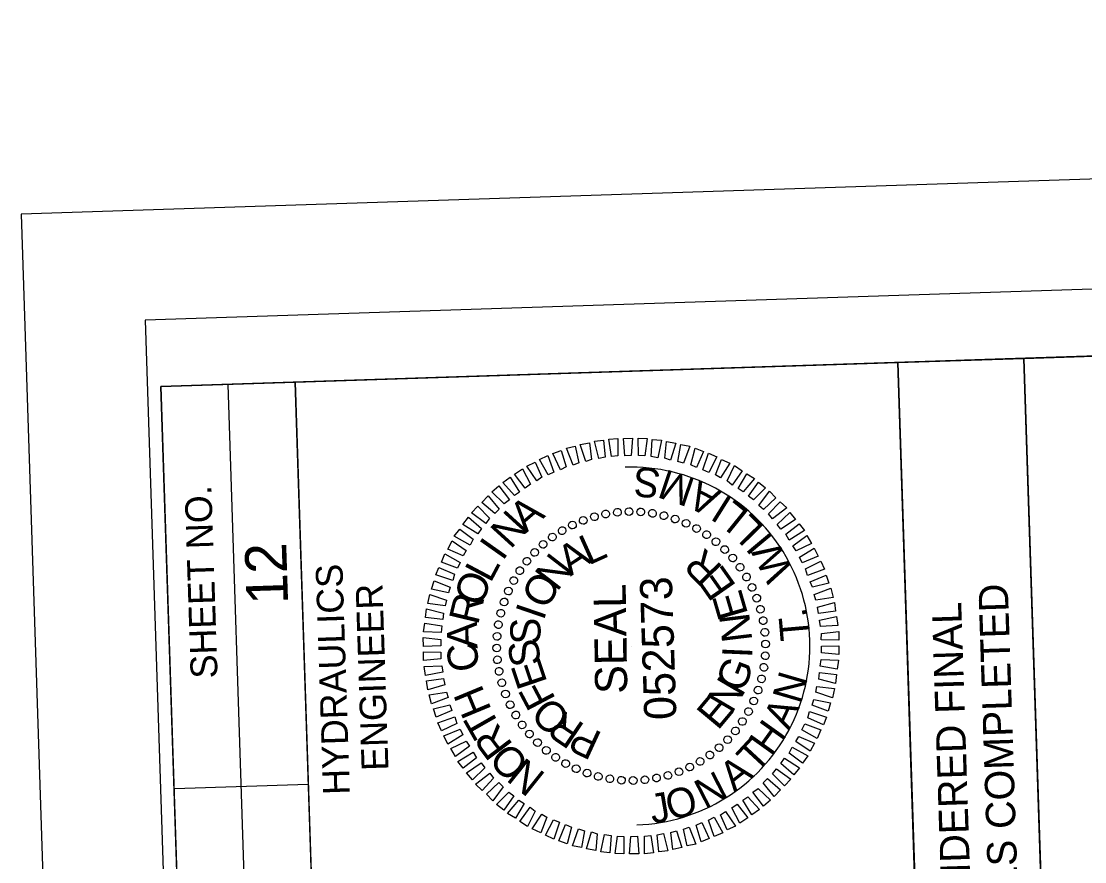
# Model space of a CAD drawing. Extents: x 1627314 to 1628469, y 762309 to 764245.
# Drawn here: x 1627314.2 to 1627512.6, y 763887.6 to 764044.4 of the extents above; entities that cross this region are included whole.
import ezdxf

# ---------------------------------------------------------------- set-up
doc = ezdxf.new("R2010")
doc.units = 0
for name, color, linetype in [('Old_Level_2', 7, 'Continuous'), ('Old_Level_58', 7, 'Continuous'), ('Scratch_Level_0', 7, 'Continuous'), ('Sheet Data Field CELL', 7, 'Continuous'), ('Sheet Plot Border Inside CELL', 7, 'Continuous'), ('Sheet Plot Border Outside CELL', 7, 'Continuous'), ('Sheet Professional Seal CELL', 7, 'Continuous'), ('Sheet Profile CELL', 7, 'Continuous'), ('Sheet Profile Grid Major CELL', 7, 'Continuous'), ('Sheet Profile Grid Minor CELL', 7, 'Continuous'), ('Sheet Sticker Exception Certification CELL', 7, 'Continuous')]:
    doc.layers.add(name, color=color, linetype=linetype)

msp = doc.modelspace()

# ---------------------------------------------------------------- linework, layer by layer
at = {"layer": 'Old_Level_2'}
msp.add_lwpolyline([(1627507.79, 763781.61), (1627501.25, 763981.49), (1627565.16, 763983.58), (1627571.7, 763783.7)], close=True, dxfattribs=at)
at = {"layer": 'Scratch_Level_0'}
msp.add_arc((1627428, 763927.84), 33.36, 271.8735, 91.8735, dxfattribs=at)
at = {"layer": 'Sheet Plot Border Inside CELL'}
msp.add_lwpolyline([(1628446.34, 762357.53), (1628391.86, 764023.14), (1627337.33, 763988.65), (1627391.81, 762323.04)], close=True, dxfattribs=at)
at = {"layer": 'Sheet Plot Border Outside CELL'}
msp.add_lwpolyline([(1628469.21, 762345.27), (1628413.63, 764044.37), (1627314.22, 764008.4), (1627369.79, 762309.31)], close=True, dxfattribs=at)
at = {"layer": 'Sheet Professional Seal CELL'}
for p, q in [((1627421.1, 763951.98), (1627421.1, 763951.98)), ((1627423.29, 763952.45), (1627423.29, 763952.45)), ((1627425.43, 763952.82), (1627425.43, 763952.82)), ((1627427.62, 763952.94), (1627427.62, 763952.94)), ((1627429.83, 763952.86), (1627429.83, 763952.86)), ((1627431.99, 763952.58), (1627431.99, 763952.58)), ((1627434.1, 763952.2), (1627434.1, 763952.2)), ((1627436.22, 763951.57), (1627436.22, 763951.57)), ((1627417.05, 763950.44), (1627417.05, 763950.44)), ((1627419.02, 763951.31), (1627419.02, 763951.31)), ((1627438.25, 763950.74), (1627438.25, 763950.74)), ((1627440.23, 763949.8), (1627440.23, 763949.8)), ((1627413.27, 763948.17), (1627413.27, 763948.17)), ((1627415.13, 763949.38), (1627415.13, 763949.38)), ((1627442.07, 763948.61), (1627442.07, 763948.61)), ((1627411.56, 763946.86), (1627411.56, 763946.86)), ((1627443.87, 763947.32), (1627443.87, 763947.32)), ((1627445.47, 763945.87), (1627445.47, 763945.87)), ((1627408.52, 763943.71), (1627408.52, 763943.71)), ((1627409.96, 763945.31), (1627409.96, 763945.31)), ((1627447.02, 763944.27), (1627447.02, 763944.27)), ((1627407.22, 763941.92), (1627407.22, 763941.92)), ((1627448.33, 763942.56), (1627448.33, 763942.56)), ((1627406.03, 763940.08), (1627406.03, 763940.08)), ((1627449.54, 763940.7), (1627449.54, 763940.7)), ((1627405.1, 763938.1), (1627405.1, 763938.1)), ((1627450.6, 763938.78), (1627450.6, 763938.78)), ((1627404.26, 763936.07), (1627404.26, 763936.07)), ((1627451.46, 763936.81), (1627451.46, 763936.81)), ((1627403.63, 763933.95), (1627403.63, 763933.95)), ((1627452.13, 763934.73), (1627452.13, 763934.73)), ((1627403.25, 763931.83), (1627403.25, 763931.83)), ((1627452.6, 763932.55), (1627452.6, 763932.55)), ((1627402.97, 763929.67), (1627402.97, 763929.67)), ((1627452.98, 763930.41), (1627452.98, 763930.41)), ((1627428, 763927.84), (1627428, 763927.84)), ((1627453.1, 763928.21), (1627453.1, 763928.21)), ((1627402.89, 763927.47), (1627402.89, 763927.47)), ((1627453.02, 763926.01), (1627453.02, 763926.01)), ((1627403.02, 763925.27), (1627403.02, 763925.27)), ((1627452.74, 763923.85), (1627452.74, 763923.85)), ((1627403.39, 763923.13), (1627403.39, 763923.13)), ((1627452.36, 763921.73), (1627452.36, 763921.73)), ((1627403.86, 763920.95), (1627403.86, 763920.95)), ((1627404.53, 763918.87), (1627404.53, 763918.87)), ((1627451.73, 763919.61), (1627451.73, 763919.61)), ((1627405.39, 763916.89), (1627405.39, 763916.89)), ((1627450.89, 763917.58), (1627450.89, 763917.58)), ((1627406.45, 763914.98), (1627406.45, 763914.98)), ((1627448.77, 763913.76), (1627448.77, 763913.76)), ((1627449.96, 763915.6), (1627449.96, 763915.6)), ((1627407.67, 763913.12), (1627407.67, 763913.12)), ((1627447.47, 763911.97), (1627447.47, 763911.97)), ((1627408.97, 763911.41), (1627408.97, 763911.41)), ((1627410.53, 763909.81), (1627410.53, 763909.81)), ((1627446.03, 763910.37), (1627446.03, 763910.37)), ((1627412.12, 763908.36), (1627412.12, 763908.36)), ((1627444.43, 763908.82), (1627444.43, 763908.82)), ((1627413.92, 763907.07), (1627413.92, 763907.07)), ((1627415.76, 763905.88), (1627415.76, 763905.88)), ((1627440.86, 763906.3), (1627440.86, 763906.3)), ((1627442.72, 763907.51), (1627442.72, 763907.51)), ((1627417.74, 763904.94), (1627417.74, 763904.94)), ((1627419.77, 763904.11), (1627419.77, 763904.11)), ((1627436.97, 763904.37), (1627436.97, 763904.37)), ((1627438.94, 763905.23), (1627438.94, 763905.23)), ((1627421.89, 763903.48), (1627421.89, 763903.48)), ((1627424, 763903.09), (1627424, 763903.09)), ((1627426.16, 763902.82), (1627426.16, 763902.82)), ((1627428.37, 763902.74), (1627428.37, 763902.74)), ((1627430.56, 763902.86), (1627430.56, 763902.86)), ((1627432.7, 763903.23), (1627432.7, 763903.23)), ((1627434.89, 763903.7), (1627434.89, 763903.7))]:
    msp.add_line(p, q, dxfattribs=at)
for points in [[(1627419.57, 763962.28), (1627418.51, 763965.4), (1627420.2, 763965.75), (1627420.6, 763962.62)], [(1627421.95, 763962.81), (1627421.14, 763966.03), (1627422.84, 763966.24), (1627423.14, 763963.05)], [(1627424.34, 763963.19), (1627423.83, 763966.42), (1627425.53, 763966.58), (1627425.53, 763963.33)], [(1627426.84, 763963.32), (1627426.58, 763966.56), (1627428.28, 763966.62), (1627428.03, 763963.36)], [(1627429.34, 763963.35), (1627429.33, 763966.6), (1627430.98, 763966.56), (1627430.54, 763963.29)], [(1627431.74, 763963.18), (1627431.94, 763966.39), (1627433.64, 763966.24), (1627432.95, 763962.97)], [(1627434.3, 763962.86), (1627434.6, 763965.97), (1627436.31, 763965.68), (1627435.37, 763962.5)], [(1627436.72, 763962.29), (1627437.27, 763965.41), (1627438.93, 763965.12), (1627437.79, 763961.93)], [(1627412.49, 763959.75), (1627410.9, 763962.65), (1627412.48, 763963.35), (1627413.58, 763960.28)], [(1627414.81, 763960.72), (1627413.41, 763963.73), (1627414.95, 763964.33), (1627415.85, 763961.26)], [(1627417.19, 763961.6), (1627415.93, 763964.76), (1627417.57, 763965.12), (1627418.22, 763961.99)], [(1627439.15, 763961.62), (1627439.95, 763964.75), (1627441.52, 763964.15), (1627440.21, 763961.11)], [(1627441.38, 763960.69), (1627442.43, 763963.83), (1627444, 763963.13), (1627442.49, 763960.23)], [(1627410.38, 763958.68), (1627408.54, 763961.42), (1627410.07, 763962.12), (1627411.31, 763959.31)], [(1627443.71, 763959.77), (1627444.87, 763962.66), (1627446.44, 763961.96), (1627444.68, 763959.2)], [(1627445.9, 763958.64), (1627447.31, 763961.49), (1627448.74, 763960.53), (1627446.82, 763957.87)], [(1627408.22, 763957.31), (1627406.24, 763959.89), (1627407.7, 763960.89), (1627409.2, 763958.04)], [(1627447.95, 763957.21), (1627449.56, 763959.96), (1627451.04, 763959.06), (1627448.92, 763956.59)], [(1627404.32, 763954.38), (1627401.99, 763956.6), (1627403.31, 763957.7), (1627405.29, 763955.11)], [(1627406.22, 763955.94), (1627404.04, 763958.32), (1627405.45, 763959.32), (1627407.15, 763956.57)], [(1627449.89, 763955.77), (1627451.76, 763958.43), (1627453.09, 763957.37), (1627450.82, 763955.1)], [(1627402.57, 763952.57), (1627400.15, 763954.64), (1627401.31, 763955.88), (1627403.35, 763953.35)], [(1627451.85, 763954.08), (1627453.82, 763956.7), (1627455.01, 763955.49), (1627452.68, 763953.31)], [(1627400.88, 763950.71), (1627398.22, 763952.68), (1627399.38, 763953.92), (1627401.6, 763951.69)], [(1627453.65, 763952.49), (1627455.78, 763954.76), (1627457.02, 763953.6), (1627454.38, 763951.56)], [(1627399.4, 763948.76), (1627396.59, 763950.52), (1627397.64, 763951.86), (1627400.06, 763949.74)], [(1627455.27, 763950.54), (1627457.6, 763952.77), (1627458.69, 763951.45), (1627455.95, 763949.61)], [(1627397.96, 763946.67), (1627395.01, 763948.32), (1627396.02, 763949.65), (1627398.53, 763947.79)], [(1627456.83, 763948.69), (1627459.32, 763950.62), (1627460.31, 763949.36), (1627457.46, 763947.61)], [(1627396.68, 763944.67), (1627393.79, 763945.93), (1627394.59, 763947.46), (1627397.25, 763945.64)], [(1627458.15, 763946.53), (1627460.79, 763948.47), (1627461.64, 763946.95), (1627458.78, 763945.6)], [(1627459.42, 763944.42), (1627462.17, 763946.12), (1627462.92, 763944.59), (1627459.91, 763943.34)], [(1627395.6, 763942.34), (1627392.62, 763943.49), (1627393.26, 763945.06), (1627396.12, 763943.45)], [(1627460.54, 763942.26), (1627463.4, 763943.65), (1627464.05, 763942.17), (1627460.88, 763941.02)], [(1627394.73, 763940.06), (1627391.54, 763941.1), (1627392.1, 763942.52), (1627395.04, 763941.22)], [(1627393.9, 763937.78), (1627390.78, 763938.43), (1627391.23, 763939.99), (1627394.22, 763938.84)], [(1627461.42, 763939.84), (1627464.38, 763941.08), (1627464.88, 763939.55), (1627461.81, 763938.8)], [(1627462.15, 763937.46), (1627465.26, 763938.61), (1627465.67, 763936.92), (1627462.43, 763936.42)], [(1627393.33, 763935.36), (1627390.07, 763935.75), (1627390.41, 763937.46), (1627393.55, 763936.42)], [(1627462.78, 763935.08), (1627465.95, 763935.98), (1627466.15, 763934.34), (1627462.97, 763933.88)], [(1627392.86, 763932.79), (1627389.65, 763933.14), (1627389.85, 763934.79), (1627392.98, 763934)], [(1627392.54, 763930.38), (1627389.29, 763930.47), (1627389.53, 763932.13), (1627392.7, 763931.59)], [(1627463.16, 763932.69), (1627466.34, 763933.34), (1627466.59, 763931.65), (1627463.34, 763931.5)], [(1627463.49, 763930.2), (1627466.73, 763930.56), (1627466.73, 763928.91), (1627463.48, 763929)], [(1627392.48, 763927.88), (1627389.23, 763927.77), (1627389.22, 763929.42), (1627392.49, 763929.08)], [(1627463.52, 763927.8), (1627466.76, 763927.91), (1627466.77, 763926.26), (1627463.51, 763926.6)], [(1627392.5, 763925.48), (1627389.26, 763925.12), (1627389.26, 763926.77), (1627392.51, 763926.68)], [(1627392.84, 763922.99), (1627389.66, 763922.33), (1627389.4, 763924.02), (1627392.65, 763924.18)], [(1627463.45, 763925.3), (1627466.7, 763925.2), (1627466.46, 763923.54), (1627463.29, 763924.09)], [(1627393.21, 763920.6), (1627390.04, 763919.69), (1627389.84, 763921.34), (1627393.02, 763921.79)], [(1627463.13, 763922.88), (1627466.34, 763922.54), (1627466.14, 763920.88), (1627463.02, 763921.68)], [(1627462.66, 763920.32), (1627465.92, 763919.92), (1627465.58, 763918.21), (1627462.44, 763919.26)], [(1627393.84, 763918.22), (1627390.73, 763917.06), (1627390.32, 763918.75), (1627393.56, 763919.26)], [(1627462.09, 763917.9), (1627465.21, 763917.25), (1627464.76, 763915.68), (1627461.77, 763916.84)], [(1627394.57, 763915.84), (1627391.61, 763914.59), (1627391.11, 763916.13), (1627394.19, 763916.88)], [(1627395.45, 763913.42), (1627392.59, 763912.02), (1627391.95, 763913.5), (1627395.11, 763914.66)], [(1627461.26, 763915.62), (1627464.45, 763914.57), (1627463.89, 763913.15), (1627460.95, 763914.46)], [(1627396.57, 763911.25), (1627393.82, 763909.56), (1627393.07, 763911.09), (1627396.09, 763912.34)], [(1627460.39, 763913.34), (1627463.38, 763912.19), (1627462.73, 763910.61), (1627459.87, 763912.22)], [(1627397.84, 763909.14), (1627395.2, 763907.21), (1627394.35, 763908.73), (1627397.21, 763910.07)], [(1627459.31, 763911), (1627462.21, 763909.75), (1627461.4, 763908.22), (1627458.74, 763910.03)], [(1627399.16, 763906.98), (1627396.67, 763905.05), (1627395.68, 763906.32), (1627398.53, 763908.06)], [(1627458.03, 763909.01), (1627460.98, 763907.36), (1627459.98, 763906.02), (1627457.46, 763907.89)], [(1627400.72, 763905.13), (1627398.39, 763902.91), (1627397.3, 763904.22), (1627400.04, 763906.06)], [(1627456.6, 763906.91), (1627459.4, 763905.15), (1627458.35, 763903.82), (1627455.93, 763905.94)], [(1627402.34, 763903.19), (1627400.21, 763900.92), (1627398.97, 763902.08), (1627401.61, 763904.11)], [(1627455.11, 763904.96), (1627457.77, 763903), (1627456.61, 763901.76), (1627454.39, 763903.99)], [(1627404.14, 763901.59), (1627402.18, 763898.98), (1627400.99, 763900.19), (1627403.32, 763902.37)], [(1627453.42, 763903.11), (1627455.84, 763901.03), (1627454.68, 763899.8), (1627452.64, 763902.33)], [(1627406.1, 763899.91), (1627404.23, 763897.25), (1627402.9, 763898.3), (1627405.17, 763900.58)], [(1627451.68, 763901.3), (1627454, 763899.07), (1627452.68, 763897.98), (1627450.7, 763900.57)], [(1627408.05, 763898.47), (1627406.43, 763895.72), (1627404.95, 763896.62), (1627407.07, 763899.09)], [(1627447.77, 763898.37), (1627449.76, 763895.78), (1627448.29, 763894.78), (1627446.79, 763897.64)], [(1627449.78, 763899.74), (1627451.95, 763897.36), (1627450.54, 763896.36), (1627448.85, 763899.1)], [(1627410.09, 763897.04), (1627408.69, 763894.19), (1627407.25, 763895.14), (1627409.17, 763897.81)], [(1627412.28, 763895.91), (1627411.12, 763893.02), (1627409.55, 763893.72), (1627411.31, 763896.48)], [(1627443.5, 763895.93), (1627445.09, 763893.03), (1627443.51, 763892.33), (1627442.41, 763895.39)], [(1627445.61, 763897), (1627447.45, 763894.26), (1627445.93, 763893.56), (1627444.68, 763896.37)], [(1627414.61, 763894.98), (1627413.56, 763891.85), (1627411.99, 763892.55), (1627413.5, 763895.45)], [(1627416.84, 763894.06), (1627416.05, 763890.93), (1627414.48, 763891.53), (1627415.78, 763894.57)], [(1627438.81, 763894.07), (1627440.06, 763890.91), (1627438.42, 763890.56), (1627437.77, 763893.69)], [(1627441.18, 763894.95), (1627442.58, 763891.95), (1627441.05, 763891.35), (1627440.14, 763894.42)], [(1627419.27, 763893.38), (1627418.72, 763890.26), (1627417.06, 763890.56), (1627418.2, 763893.75)], [(1627421.69, 763892.81), (1627421.39, 763889.7), (1627419.68, 763890), (1627420.62, 763893.18)], [(1627424.25, 763892.5), (1627424.05, 763889.29), (1627422.35, 763889.43), (1627423.04, 763892.71)], [(1627426.66, 763892.33), (1627426.66, 763889.07), (1627425.01, 763889.12), (1627425.45, 763892.39)], [(1627429.16, 763892.36), (1627429.41, 763889.11), (1627427.71, 763889.06), (1627427.96, 763892.32)], [(1627431.65, 763892.49), (1627432.16, 763889.25), (1627430.46, 763889.1), (1627430.46, 763892.35)], [(1627434.04, 763892.87), (1627434.85, 763889.64), (1627433.15, 763889.44), (1627432.85, 763892.63)], [(1627436.43, 763893.4), (1627437.48, 763890.28), (1627435.79, 763889.92), (1627435.39, 763893.06)]]:
    msp.add_lwpolyline(points, close=True, dxfattribs=at)
for centre, major_axis in [((1627425.43, 763952.79), (-0.074, 0.716)), ((1627427.61, 763952.92), (-0.011, 0.72)), ((1627429.8, 763952.85), (0.052, 0.718)), ((1627419.06, 763951.27), (-0.257, 0.673)), ((1627421.14, 763951.96), (-0.197, 0.693)), ((1627423.26, 763952.47), (-0.136, 0.707)), ((1627431.97, 763952.6), (0.114, 0.711)), ((1627434.12, 763952.16), (0.176, 0.698)), ((1627436.21, 763951.53), (0.236, 0.68)), ((1627438.25, 763950.73), (0.294, 0.657)), ((1627415.13, 763949.36), (-0.369, 0.618)), ((1627417.05, 763950.4), (-0.314, 0.648)), ((1627440.2, 763949.75), (0.35, 0.629)), ((1627411.58, 763946.8), (-0.471, 0.544)), ((1627413.3, 763948.16), (-0.422, 0.583)), ((1627442.07, 763948.6), (0.404, 0.596)), ((1627443.82, 763947.29), (0.454, 0.559)), ((1627409.99, 763945.3), (-0.517, 0.501)), ((1627445.46, 763945.84), (0.501, 0.517)), ((1627408.54, 763943.66), (-0.559, 0.454)), ((1627446.96, 763944.25), (0.544, 0.471)), ((1627407.23, 763941.91), (-0.596, 0.404)), ((1627448.32, 763942.54), (0.583, 0.422)), ((1627449.52, 763940.71), (0.618, 0.369)), ((1627406.09, 763940.05), (-0.629, 0.35)), ((1627450.56, 763938.78), (0.648, 0.314)), ((1627405.11, 763938.09), (-0.657, 0.294)), ((1627451.43, 763936.77), (0.673, 0.257)), ((1627404.3, 763936.06), (-0.68, 0.236)), ((1627403.67, 763933.96), (-0.698, 0.176)), ((1627452.12, 763934.7), (0.693, 0.197)), ((1627403.23, 763931.82), (-0.711, 0.114)), ((1627452.63, 763932.57), (0.707, 0.136)), ((1627402.98, 763929.64), (-0.718, 0.052)), ((1627452.94, 763930.4), (0.716, 0.074)), ((1627402.92, 763927.46), (-0.72, -0.011)), ((1627453.07, 763928.22), (0.72, 0.011)), ((1627403.05, 763925.27), (-0.716, -0.074)), ((1627453.01, 763926.03), (0.718, -0.052)), ((1627403.37, 763923.11), (-0.707, -0.136)), ((1627452.76, 763923.86), (0.711, -0.114)), ((1627403.87, 763920.98), (-0.693, -0.197)), ((1627452.32, 763921.72), (0.698, -0.176)), ((1627404.56, 763918.9), (-0.673, -0.257)), ((1627451.69, 763919.62), (0.68, -0.236)), ((1627405.43, 763916.89), (-0.648, -0.314)), ((1627450.88, 763917.59), (0.657, -0.294)), ((1627406.47, 763914.97), (-0.618, -0.369)), ((1627449.9, 763915.63), (0.629, -0.35)), ((1627407.67, 763913.14), (-0.583, -0.422)), ((1627448.76, 763913.77), (0.596, -0.404)), ((1627409.03, 763911.43), (-0.544, -0.471)), ((1627447.45, 763912.01), (0.559, -0.454)), ((1627410.53, 763909.84), (-0.501, -0.517)), ((1627446, 763910.38), (0.517, -0.501)), ((1627412.17, 763908.38), (-0.454, -0.559)), ((1627413.93, 763907.08), (-0.404, -0.596)), ((1627442.69, 763907.52), (0.422, -0.583)), ((1627444.41, 763908.87), (0.471, -0.544)), ((1627415.79, 763905.93), (-0.35, -0.629)), ((1627438.94, 763905.27), (0.314, -0.648)), ((1627440.87, 763906.31), (0.369, -0.618)), ((1627417.74, 763904.95), (-0.294, -0.657)), ((1627419.78, 763904.14), (-0.236, -0.68)), ((1627421.87, 763903.52), (-0.176, -0.698)), ((1627424.02, 763903.08), (-0.114, -0.711)), ((1627432.73, 763903.21), (0.136, -0.707)), ((1627434.86, 763903.71), (0.197, -0.693)), ((1627436.93, 763904.4), (0.257, -0.673)), ((1627426.19, 763902.82), (-0.052, -0.718)), ((1627428.38, 763902.76), (0.011, -0.72)), ((1627430.56, 763902.89), (0.074, -0.716))]:
    msp.add_ellipse(centre, major_axis=major_axis, ratio=0.999708, dxfattribs=at)
at = {"layer": 'Sheet Profile CELL'}
for p, q in [((1627359.37, 763776.71), (1627352.83, 763976.65)), ((1627342.78, 763901.28), (1627367.77, 763902.1))]:
    msp.add_line(p, q, dxfattribs=at)
for points in [[(1627340.28, 763976.24), (1627389.32, 762477.04), (1628438.76, 762511.37), (1628389.72, 764010.57)], [(1627368.59, 763877.11), (1627365.32, 763977.06), (1627477.76, 763980.74), (1627481.03, 763880.79)], [(1627346.82, 763776.3), (1627340.28, 763976.24), (1627365.32, 763977.06), (1627371.86, 763777.12)]]:
    msp.add_lwpolyline(points, close=True, dxfattribs=at)
at = {"layer": 'Sheet Profile Grid Major CELL'}
msp.add_lwpolyline([(1627566.8, 763933.62), (1627841.65, 763942.61), (1627840.02, 763992.59), (1627490.2, 763981.14)], dxfattribs=at)
at = {"layer": 'Sheet Sticker Exception Certification CELL'}
for p, q in [((1627477.77, 763980.72), (1627501.26, 763981.49)), ((1627477.77, 763980.72), (1627501.26, 763981.49)), ((1627501.25, 763981.49), (1627507.79, 763781.56)), ((1627501.25, 763981.49), (1627507.79, 763781.56)), ((1627484.3, 763780.79), (1627477.76, 763980.72)), ((1627484.3, 763780.79), (1627477.76, 763980.72))]:
    msp.add_line(p, q, dxfattribs=at)

# ---------------------------------------------------------------- texts
at = {"layer": 'Old_Level_58'}
for s, rotation, p in [('S', 173.0617, (1627433.71, 763960.75)), ('M', 161.4413, (1627440.22, 763958.93)), ('A', 152.311, (1627445, 763956.6)), ('I', 147.846, (1627447.18, 763955.18)), ('L', 141.0913, (1627450.27, 763952.74)), ('L', 134.3366, (1627453.04, 763949.94)), ('I', 129.8716, (1627454.69, 763947.93)), ('W', 117.321, (1627458.41, 763941.65)), ('.', 102.2517, (1627460.96, 763933.26)), ('T', 95.0104, (1627461.38, 763929.07)), ('N', 73.7445, (1627459.55, 763916.87)), ('A', 64.6142, (1627457.41, 763912.01)), ('H', 54.4249, (1627454.15, 763907.05)), ('T', 47.1836, (1627451.32, 763903.92)), ('A', 38.0533, (1627447.23, 763900.52)), ('N', 27.1771, (1627441.73, 763897.38)), ('J', 9.715, (1627431.96, 763894.67)), ('O', 15.528, (1627435.3, 763895.24))]:
    msp.add_text(s, height=5.5, rotation=rotation, dxfattribs=at).set_placement(p)
at = {"layer": 'Sheet Data Field CELL'}
msp.add_text('12', height=7.75, rotation=91.8735, dxfattribs=at).set_placement((1627364.01, 763935.7))
at = {"layer": 'Sheet Professional Seal CELL'}
for s, height, rotation, p in [('A', 5.64, 40.4906, (1627408.35, 763948.81)), ('N', 5.64, 47.6924, (1627405.5, 763945.76)), ('I', 5.64, 54.8936, (1627404.02, 763943.56)), ('L', 5.64, 24.2743, (1627420.05, 763942.84)), ('A', 5.64, 33.6337, (1627416.67, 763940.77)), ('R', 5.64, 134.3549, (1627445.28, 763942.51)), ('N', 5.64, 52.3501, (1627414.16, 763937.84)), ('L', 5.64, 62.0943, (1627401.75, 763939.44)), ('E', 5.64, 124.9976, (1627447.74, 763939.04)), ('O', 5.64, 69.2946, (1627400.05, 763934.98)), ('O', 5.64, 61.707, (1627412.27, 763934.43)), ('SEAL', 5.998, 90.8735, (1627427.29, 763918.96)), ('E', 5.64, 106.2852, (1627449.86, 763933.81)), ('R', 5.64, 76.4946, (1627399.41, 763931.61)), ('I', 5.64, 71.0631, (1627411.64, 763932.41)), ('N', 5.64, 96.9299, (1627450.62, 763928.88)), ('A', 5.64, 90.8938, (1627399.34, 763927.4)), ('S', 5.64, 89.7739, (1627411.08, 763928.09)), ('C', 5.64, 98.0933, (1627399.77, 763923.46)), ('S', 5.64, 99.1291, (1627411.25, 763924.49)), ('I', 5.64, 87.5747, (1627450.58, 763925.53)), ('E', 5.64, 108.4845, (1627412.41, 763921.08)), ('G', 5.64, 68.8637, (1627448.9, 763918.92)), ('N', 5.64, 59.5074, (1627446.77, 763915.05)), ('H', 5.64, 112.4929, (1627402.02, 763915.93)), ('F', 5.64, 117.8405, (1627414.01, 763917.93)), ('E', 5.64, 50.1504, (1627444.17, 763911.96)), ('O', 5.64, 136.5547, (1627417.07, 763914.72)), ('R', 5.64, 145.9131, (1627419.57, 763913.06)), ('T', 5.64, 119.6932, (1627403.78, 763912.74)), ('R', 5.64, 126.894, (1627406.09, 763909.41)), ('P', 5.64, 155.2724, (1627422.83, 763911.56)), ('O', 5.64, 134.0952, (1627409.3, 763906.07)), ('N', 5.64, 141.297, (1627412.27, 763903.86))]:
    msp.add_text(s, height=height, rotation=rotation, dxfattribs=at).set_placement(p)
at = {"layer": 'Sheet Profile CELL'}
for s, p in [('SHEET NO.', (1627350.85, 763921.87)), ('HYDRAULICS', (1627375.53, 763900.16)), ('ENGINEER', (1627382.73, 763904.65))]:
    msp.add_text(s, height=5, rotation=91.8735, dxfattribs=at).set_placement(p)
at = {"layer": 'Sheet Profile Grid Minor CELL'}
msp.add_text('052573', height=5.998, rotation=91.8735, dxfattribs=at).set_placement((1627436.46, 763914.15))
at = {"layer": 'Sheet Sticker Exception Certification CELL'}
for s, p in [('UNLESS ALL SIGNATURES COMPLETED', (1627502.91, 763797.41)), ('UNLESS ALL SIGNATURES COMPLETED', (1627502.91, 763797.41)), ('DOCUMENT NOT CONSIDERED FINAL', (1627493.95, 763802.19)), ('DOCUMENT NOT CONSIDERED FINAL', (1627493.95, 763802.19))]:
    msp.add_text(s, height=5.5, rotation=91.8735, dxfattribs=at).set_placement(p)

doc.saveas('drawing.dxf')
